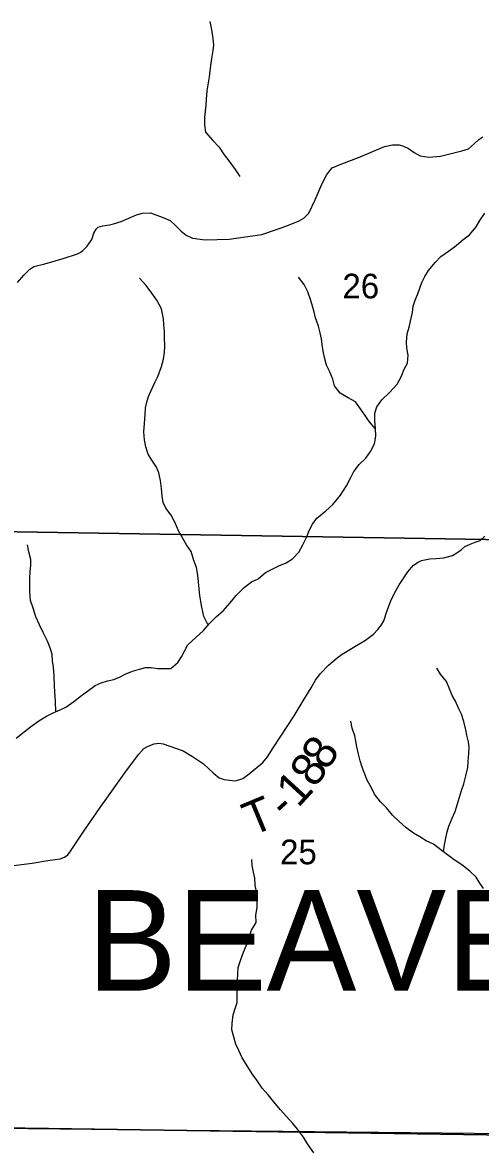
# Model space of a CAD drawing. Extents: x 2043100 to 2470832, y 443715 to 810583.
# Drawn here: x 2296308 to 2300401, y 682957 to 693056 of the extents above; entities that cross this region are included whole.
import ezdxf

# ---------------------------------------------------------------- set-up
doc = ezdxf.new("R2010")
doc.units = 0
for name, color, linetype in [('GM_X_Minor_River', 7, 'Continuous'), ('GM_X_Section', 7, 'Continuous'), ('GM_X_Section_Text', 7, 'Continuous'), ('GM_X_Township', 7, 'Continuous'), ('GM_X_Township_Road', 7, 'Continuous'), ('GM_X_Township_Road_Text', 7, 'Continuous'), ('GM_X_Township_ROW', 7, 'Continuous'), ('GM_X_Township_Text', 7, 'Continuous')]:
    doc.layers.add(name, color=color, linetype=linetype)

msp = doc.modelspace()

# ---------------------------------------------------------------- linework, layer by layer
at = {"layer": 'GM_X_Minor_River'}
for points in [[(2297982, 693066), (2297994, 693006), (2298006, 692936), (2298014, 692857), (2298008, 692807), (2297997, 692735), (2297989, 692673), (2297981, 692623), (2297975, 692569), (2297963, 692499), (2297955, 692444), (2297949, 692370), (2297945, 692314), (2297940, 692262), (2297934, 692206), (2297934, 692142), (2297944, 692074), (2298008, 692002), (2298064, 691940), (2298111, 691874), (2298161, 691808), (2298207, 691740), (2298249, 691678)], [(2299801, 690518), (2299817, 690571), (2299840, 690629), (2299860, 690679), (2299878, 690731), (2299904, 690785), (2299936, 690838), (2299996, 690908), (2300048, 690962), (2300114, 691011), (2300170, 691051), (2300244, 691113), (2300302, 691156), (2300364, 691230), (2300396, 691286), (2300440, 691350)], [(2297966, 687666), (2297927, 687742), (2297911, 687826), (2297901, 687876), (2297891, 687930), (2297887, 687991), (2297881, 688051), (2297875, 688113), (2297862, 688181), (2297840, 688243), (2297816, 688323), (2297774, 688385), (2297736, 688447), (2297703, 688509), (2297671, 688581), (2297635, 688649), (2297587, 688713), (2297565, 688763), (2297556, 688819), (2297550, 688887), (2297540, 688960), (2297526, 689028), (2297506, 689080), (2297464, 689142), (2297431, 689196), (2297409, 689260), (2297399, 689324), (2297393, 689396), (2297397, 689468), (2297403, 689550), (2297408, 689608), (2297420, 689659), (2297432, 689711), (2297456, 689765), (2297492, 689841), (2297518, 689891), (2297550, 689980), (2297568, 690044), (2297576, 690106), (2297580, 690160), (2297577, 690240), (2297575, 690292), (2297571, 690353), (2297569, 690405), (2297551, 690495), (2297508, 690573), (2297464, 690635), (2297414, 690703), (2297354, 690769)], [(2299464, 689421), (2299406, 689487), (2299370, 689541), (2299330, 689599), (2299284, 689663), (2299217, 689699), (2299147, 689741), (2299097, 689807), (2299081, 689865), (2299051, 689937), (2299024, 689991), (2299008, 690061), (2298994, 690117), (2298986, 690175), (2298980, 690227), (2298968, 690281), (2298952, 690339), (2298927, 690415), (2298915, 690465), (2298901, 690519), (2298885, 690569), (2298857, 690646), (2298824, 690714), (2298774, 690778)], [(2296251, 686654), (2296321, 686711), (2296379, 686757), (2296453, 686809), (2296521, 686850), (2296575, 686878), (2296643, 686908), (2296695, 686932), (2296767, 686983), (2296835, 687037), (2296887, 687075), (2296957, 687124), (2297011, 687148), (2297067, 687166), (2297123, 687180), (2297175, 687201), (2297225, 687227), (2297289, 687253), (2297353, 687271), (2297408, 687286), (2297458, 687286), (2297514, 687278), (2297634, 687278), (2297696, 687331), (2297728, 687383), (2297758, 687439), (2297786, 687489), (2297856, 687556), (2297924, 687616), (2297978, 687680), (2298042, 687743), (2298100, 687793), (2298164, 687865), (2298216, 687930), (2298288, 688002), (2298354, 688052), (2298414, 688079), (2298480, 688135), (2298550, 688173), (2298600, 688195), (2298664, 688224), (2298720, 688258), (2298776, 688318), (2298812, 688383), (2298849, 688455), (2298871, 688513), (2298901, 688569), (2298939, 688623), (2299019, 688688), (2299081, 688746), (2299151, 688827), (2299203, 688911), (2299241, 688985), (2299269, 689039), (2299317, 689102), (2299375, 689158), (2299419, 689220), (2299455, 689287), (2299465, 689355), (2299464, 689423), (2299458, 689493), (2299458, 689561), (2299476, 689619), (2299518, 689682), (2299590, 689750), (2299656, 689820), (2299692, 689887), (2299720, 689955), (2299748, 690009), (2299756, 690079), (2299743, 690143), (2299739, 690198), (2299747, 690272), (2299763, 690332), (2299777, 690384), (2299793, 690462), (2299801, 690518)], [(2296605, 686891), (2296603, 686984), (2296595, 687066), (2296594, 687124), (2296590, 687211), (2296584, 687289), (2296576, 687345), (2296572, 687403), (2296556, 687453), (2296531, 687521), (2296491, 687601), (2296459, 687669), (2296427, 687741), (2296401, 687817), (2296378, 687885), (2296372, 687962), (2296372, 688086), (2296376, 688146), (2296382, 688198), (2296380, 688254), (2296365, 688320), (2296351, 688384)], [(2300072, 685637), (2300080, 685699), (2300092, 685759), (2300104, 685815), (2300119, 685866), (2300149, 685938), (2300175, 685998), (2300215, 686127), (2300233, 686185), (2300253, 686247), (2300271, 686317), (2300289, 686393), (2300292, 686447), (2300298, 686516), (2300300, 686570), (2300294, 686620), (2300280, 686680), (2300270, 686730), (2300254, 686804), (2300231, 686868), (2300209, 686918), (2300179, 686984), (2300147, 687036), (2300123, 687096), (2300097, 687162), (2300044, 687226), (2300012, 687280)], [(2300429, 685308), (2300397, 685358), (2300363, 685412), (2300305, 685465), (2300234, 685521), (2300166, 685567), (2300096, 685621), (2300046, 685655), (2299980, 685707), (2299917, 685737), (2299859, 685771), (2299803, 685804), (2299735, 685856), (2299673, 685908), (2299614, 685964), (2299562, 686030), (2299508, 686086), (2299454, 686154), (2299431, 686204), (2299387, 686280), (2299363, 686346), (2299345, 686396), (2299325, 686452), (2299311, 686510), (2299296, 686576), (2299288, 686626), (2299278, 686676), (2299254, 686743), (2299242, 686807)], [(2298394, 685072), (2298404, 685140), (2298406, 685190), (2298398, 685279), (2298388, 685339), (2298383, 685401), (2298373, 685457), (2298361, 685515), (2298357, 685569)], [(2298912, 682945), (2298854, 683024), (2298818, 683084), (2298767, 683156), (2298725, 683208), (2298663, 683274), (2298614, 683329), (2298552, 683403), (2298504, 683463), (2298451, 683523), (2298403, 683594), (2298361, 683652), (2298308, 683738), (2298270, 683796), (2298241, 683860), (2298215, 683916), (2298193, 683992), (2298178, 684044), (2298182, 684102), (2298190, 684178), (2298207, 684236), (2298227, 684290), (2298226, 684372), (2298228, 684431), (2298228, 684489), (2298232, 684543), (2298235, 684603), (2298259, 684675), (2298282, 684739), (2298314, 684810), (2298328, 684860), (2298353, 684936), (2298397, 685004), (2298394, 685072)]]:
    msp.add_lwpolyline(points, dxfattribs=at)
at = {"layer": 'GM_X_Section'}
for points in [[(2296167, 693933), (2301611, 693839), (2301544, 688414), (2296075, 688502)], [(2296075, 688502), (2301544, 688414), (2301482, 683106), (2296069, 683161)]]:
    msp.add_lwpolyline(points, close=True, dxfattribs=at)
at = {"layer": 'GM_X_Township'}
for points in [[(2309205, 683004), (2305696, 683037), (2302497, 683068), (2301478, 683091), (2300660, 683103), (2295712, 683175), (2293608, 683205), (2293648, 685708), (2293731, 693440)], [(2291163, 672835), (2291207, 678355), (2291155, 683246), (2293608, 683205), (2295712, 683175), (2300660, 683103), (2301478, 683091), (2301452, 681110), (2301434, 679295), (2301360, 674291)]]:
    msp.add_lwpolyline(points, dxfattribs=at)
at = {"layer": 'GM_X_Township_Road'}
msp.add_lwpolyline([(2296183, 685509), (2296393, 685536), (2296533, 685560), (2296645, 685576), (2296683, 685591), (2296713, 685611), (2296735, 685643), (2296854, 685822), (2297000, 686034), (2297245, 686376), (2297347, 686510), (2297391, 686563), (2297429, 686583), (2297485, 686605), (2297527, 686611), (2297565, 686605), (2297743, 686542), (2297827, 686490), (2297924, 686424), (2298016, 686342), (2298064, 686300), (2298110, 686284), (2298158, 686278), (2298210, 686274), (2298278, 686293), (2298332, 686335), (2298456, 686438), (2298498, 686488), (2298548, 686568), (2298735, 686855), (2298815, 686988), (2298887, 687104), (2298927, 687174), (2298967, 687231), (2299044, 687307), (2299120, 687373), (2299166, 687406), (2299262, 687464), (2299372, 687531), (2299444, 687585), (2299484, 687625), (2299516, 687667), (2299538, 687705), (2299568, 687796), (2299601, 687884), (2299631, 687946), (2299673, 688025), (2299751, 688143), (2299803, 688203), (2299843, 688229), (2299875, 688244), (2299949, 688258), (2300003, 688262), (2300075, 688268), (2300151, 688287), (2300191, 688313), (2300229, 688339), (2300261, 688369), (2300281, 688379), (2300309, 688391), (2300355, 688407), (2300399, 688424), (2300439, 688462)], dxfattribs=at)
at = {"layer": 'GM_X_Township_ROW'}
msp.add_lwpolyline([(2296262, 690732), (2296318, 690796), (2296372, 690849), (2296408, 690873), (2296506, 690899), (2296670, 690944), (2296798, 690986), (2296822, 690998), (2296846, 691016), (2296886, 691057), (2296926, 691115), (2296946, 691171), (2296966, 691209), (2296982, 691225), (2297024, 691237), (2297084, 691246), (2297122, 691256), (2297188, 691276), (2297326, 691337), (2297380, 691351), (2297450, 691353), (2297556, 691315), (2297628, 691285), (2297674, 691241), (2297725, 691191), (2297769, 691153), (2297827, 691128), (2297941, 691112), (2298155, 691117), (2298447, 691161), (2298629, 691222), (2298686, 691244), (2298779, 691281), (2298823, 691307), (2298867, 691351), (2298923, 691470), (2298983, 691610), (2299026, 691692), (2299052, 691727), (2299076, 691755), (2299148, 691785), (2299326, 691854), (2299542, 691946), (2299614, 691963), (2299674, 691961), (2299714, 691949), (2299759, 691929), (2299809, 691893), (2299863, 691865), (2299941, 691851), (2300043, 691862), (2300235, 691907), (2300293, 691925), (2300349, 691973), (2300387, 692011), (2300423, 692035)], dxfattribs=at)

# ---------------------------------------------------------------- texts
at = {"layer": 'GM_X_Section_Text'}
for s, p in [('26', (2299167, 690588)), ('25', (2298610, 685526))]:
    msp.add_text(s, height=220.8, rotation=0, dxfattribs=at).set_placement(p)
at = {"layer": 'GM_X_Township_Road_Text'}
for s, rotation, p in [('8', 56.5481, (2299029, 686356)), ('8', 56.562, (2298927, 686201)), ('1', 47.4219, (2298770, 686024)), ('T', 22.5694, (2298356, 685775)), ('-', 42.1884, (2298658, 685920))]:
    msp.add_text(s, height=300, rotation=rotation, dxfattribs=at).set_placement(p)
at = {"layer": 'GM_X_Township_Text'}
msp.add_text('BEAVER', height=900, rotation=0, dxfattribs=at).set_placement((2296884, 684395))

doc.saveas('drawing.dxf')
